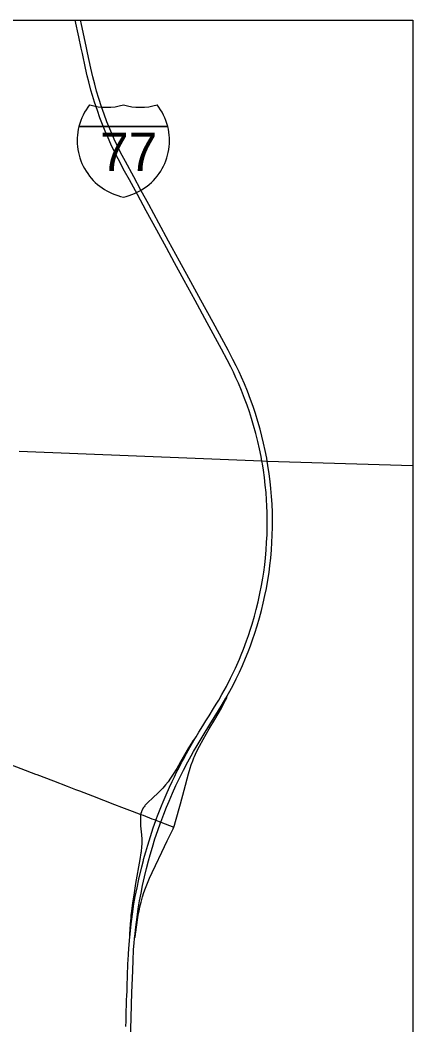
# Model space of a CAD drawing. Extents: x -12.1 to 34, y 0 to 22.
# Drawn here: x -5.572 to -4.438, y 17.405 to 20.306 of the extents above; entities that cross this region are included whole.
import ezdxf

# ---------------------------------------------------------------- set-up
doc = ezdxf.new("R2010")
doc.units = 0
for name, color, linetype in [('GM_X_Interchange_Ramps', 7, 'Continuous'), ('GM_X_Interstate_Route', 7, 'Continuous'), ('GM_X_Interstate_Shield', 7, 'Continuous'), ('GM_X_State_Route', 7, 'Continuous'), ('GM_X_Township', 7, 'Continuous'), ('SH_Text', 7, 'Continuous')]:
    doc.layers.add(name, color=color, linetype=linetype)

msp = doc.modelspace()

# ---------------------------------------------------------------- linework, layer by layer
at = {"layer": 'GM_X_Interchange_Ramps'}
for points in [[(-5.0661, 18.2332), (-5.0672, 18.2323), (-5.0686, 18.231), (-5.07, 18.2296), (-5.0728, 18.2264), (-5.0745, 18.2241), (-5.0777, 18.2186), (-5.0861, 18.2047), (-5.0973, 18.1849), (-5.109, 18.1641), (-5.1199, 18.1455), (-5.1304, 18.1287), (-5.1381, 18.117), (-5.1451, 18.107), (-5.1522, 18.0978), (-5.1603, 18.0886), (-5.1705, 18.0782), (-5.192, 18.0577), (-5.2, 18.05), (-5.2053, 18.0447), (-5.2106, 18.0392), (-5.2125, 18.0371), (-5.2143, 18.0347), (-5.2166, 18.0314), (-5.2172, 18.0304), (-5.2177, 18.0295), (-5.2181, 18.0288), (-5.2186, 18.0278), (-5.2207, 18.023), (-5.2214, 18.021), (-5.222, 18.0193), (-5.2225, 18.0179), (-5.2232, 18.015), (-5.2237, 18.0125)], [(-5.2237, 18.0125), (-5.2239, 18.0113), (-5.2241, 18.0103), (-5.2242, 18.0087), (-5.2248, 17.9955), (-5.2248, 17.9868), (-5.2245, 17.9792), (-5.2237, 17.9705), (-5.2217, 17.9532), (-5.2206, 17.941), (-5.2205, 17.9293), (-5.2212, 17.9173), (-5.2215, 17.9152), (-5.2222, 17.9097), (-5.2228, 17.9048), (-5.2233, 17.9016), (-5.2266, 17.882), (-5.2387, 17.8126), (-5.2442, 17.7793), (-5.2476, 17.7569), (-5.2507, 17.7332), (-5.252, 17.721), (-5.2528, 17.7128), (-5.2532, 17.7064), (-5.254, 17.6961), (-5.2551, 17.6807), (-5.2563, 17.6665), (-5.2566, 17.6633), (-5.2565, 17.6614), (-5.2564, 17.6594), (-5.2561, 17.6583), (-5.2557, 17.6571)], [(-5.2414, 17.656), (-5.2408, 17.657), (-5.2403, 17.6579), (-5.2399, 17.6591), (-5.2396, 17.6604), (-5.2391, 17.6636), (-5.2386, 17.6673), (-5.2379, 17.6727), (-5.233, 17.7084), (-5.2309, 17.7216), (-5.2288, 17.7331), (-5.2261, 17.7456), (-5.2228, 17.7592), (-5.2185, 17.7743), (-5.2147, 17.7866), (-5.2101, 17.7998), (-5.2048, 17.814), (-5.1986, 17.8285), (-5.1913, 17.8444), (-5.1815, 17.8649), (-5.1629, 17.9031), (-5.1471, 17.9362), (-5.138, 17.9551), (-5.1306, 17.9707), (-5.1282, 17.9761)]]:
    msp.add_lwpolyline(points, dxfattribs=at)
at = {"layer": 'GM_X_Interstate_Route'}
for points in [[(-5.0661, 18.2332), (-5.064, 18.2366), (-5.0562, 18.2496), (-5.0494, 18.2604), (-5.0415, 18.2734), (-5.0357, 18.2828), (-5.0268, 18.2972), (-5.0136, 18.3184), (-5.0061, 18.3309), (-4.9989, 18.3429), (-4.9896, 18.3591), (-4.9767, 18.3819), (-4.9644, 18.4058), (-4.9588, 18.4173), (-4.9504, 18.4352), (-4.9391, 18.4608), (-4.934, 18.4732), (-4.9275, 18.4894), (-4.9182, 18.514), (-4.9126, 18.5293), (-4.9068, 18.547), (-4.9022, 18.5615), (-4.8954, 18.585), (-4.8904, 18.6042), (-4.885, 18.6263), (-4.8798, 18.6502), (-4.8752, 18.6731), (-4.8715, 18.6943), (-4.8687, 18.7122), (-4.8661, 18.733), (-4.8639, 18.7533), (-4.8619, 18.776), (-4.8604, 18.7986), (-4.8593, 18.8202), (-4.8587, 18.8418), (-4.8586, 18.8616), (-4.8589, 18.8831), (-4.8596, 18.9035), (-4.8606, 18.921), (-4.8622, 18.9425), (-4.8643, 18.9634), (-4.8669, 18.9854), (-4.8699, 19.0067), (-4.8728, 19.0245), (-4.8743, 19.0329), (-4.8767, 19.0457), (-4.8814, 19.0686), (-4.8861, 19.0896), (-4.8919, 19.1128), (-4.898, 19.1353), (-4.9039, 19.1554), (-4.9103, 19.1754), (-4.9167, 19.1942), (-4.924, 19.2138), (-4.9331, 19.2366), (-4.9418, 19.2575), (-4.9489, 19.2735), (-4.9562, 19.2894), (-4.9637, 19.3046), (-4.9744, 19.3253), (-4.9909, 19.356), (-5.0323, 19.4323), (-5.067, 19.4963), (-5.0988, 19.5546), (-5.1263, 19.6052), (-5.1499, 19.6488), (-5.1776, 19.6994), (-5.2081, 19.7557), (-5.2335, 19.8023), (-5.2567, 19.8447), (-5.2705, 19.8703), (-5.2892, 19.9058), (-5.3002, 19.9276), (-5.3098, 19.9476), (-5.3182, 19.9661), (-5.3267, 19.9859), (-5.3343, 20.0048), (-5.3417, 20.0244), (-5.3491, 20.0452), (-5.3572, 20.0695), (-5.3632, 20.0889), (-5.3676, 20.104), (-5.3739, 20.1276), (-5.3783, 20.1457), (-5.3834, 20.1678), (-5.3923, 20.2094), (-5.3958, 20.2255), (-5.4027, 20.2578), (-5.4131, 20.3063)], [(-4.9741, 18.3554), (-4.9668, 18.3682), (-4.9575, 18.3857), (-4.9481, 18.4044), (-4.9391, 18.4233), (-4.9303, 18.443), (-4.9216, 18.4633), (-4.9139, 18.4822), (-4.9072, 18.4996), (-4.9012, 18.5166), (-4.8947, 18.5359), (-4.8878, 18.5575), (-4.8811, 18.5804), (-4.8754, 18.6012), (-4.8703, 18.6221), (-4.8653, 18.6442), (-4.8611, 18.6653), (-4.8569, 18.6894), (-4.8536, 18.7107), (-4.851, 18.7309), (-4.8486, 18.7529), (-4.8465, 18.7767), (-4.8451, 18.7976), (-4.8442, 18.8185), (-4.8436, 18.8418), (-4.8435, 18.8627), (-4.8439, 18.8848), (-4.8447, 18.9081), (-4.8461, 18.9307), (-4.848, 18.9539), (-4.8501, 18.9742), (-4.853, 18.9961), (-4.8567, 19.0203), (-4.8588, 19.0325), (-4.8603, 19.0415), (-4.8645, 19.0632), (-4.8691, 19.0842), (-4.8741, 19.1051), (-4.8794, 19.1254), (-4.8855, 19.1467), (-4.8929, 19.1706), (-4.8995, 19.1904), (-4.9068, 19.2107), (-4.916, 19.2346), (-4.9246, 19.2556), (-4.9329, 19.2748), (-4.9401, 19.2907), (-4.9482, 19.3075), (-4.9577, 19.3261), (-4.9718, 19.3529), (-5.015, 19.4328), (-5.0506, 19.4976), (-5.0847, 19.5606), (-5.1117, 19.6103), (-5.1433, 19.668), (-5.1715, 19.7196), (-5.2005, 19.7735), (-5.2234, 19.8154), (-5.244, 19.8533), (-5.2683, 19.8984), (-5.2818, 19.9242), (-5.2913, 19.9429), (-5.2973, 19.9555), (-5.3057, 19.9741), (-5.3132, 19.9918), (-5.3214, 20.0124), (-5.3296, 20.0342), (-5.3371, 20.0557), (-5.3449, 20.0801), (-5.3512, 20.1013), (-5.3566, 20.121), (-5.362, 20.1425), (-5.3678, 20.1675), (-5.3772, 20.2119), (-5.3803, 20.2258), (-5.3961, 20.2983), (-5.3978, 20.3063)], [(-5.0243, 18.2717), (-5.0115, 18.2925), (-4.9918, 18.3249), (-4.978, 18.3485), (-4.9741, 18.3554)], [(-5.1668, 17.9882), (-5.1665, 17.9891), (-5.1661, 17.9901), (-5.1572, 18.0136), (-5.1493, 18.0338), (-5.1422, 18.0509), (-5.1324, 18.0734), (-5.1223, 18.0957), (-5.1114, 18.1187), (-5.1005, 18.1401), (-5.0881, 18.1639), (-5.0784, 18.1819), (-5.0715, 18.194), (-5.0612, 18.2116), (-5.0436, 18.2405), (-5.0243, 18.2717)], [(-5.2163, 17.8792), (-5.2156, 17.882), (-5.2095, 17.9044), (-5.2038, 17.924), (-5.1961, 17.9484), (-5.1877, 17.9738), (-5.1804, 17.9947), (-5.1801, 17.9956), (-5.1735, 18.0132), (-5.1641, 18.0371), (-5.1592, 18.0489), (-5.1505, 18.0692), (-5.1405, 18.0915), (-5.1329, 18.1079), (-5.1262, 18.1215), (-5.1192, 18.1362), (-5.1142, 18.146), (-5.1058, 18.1627), (-5.1005, 18.1724), (-5.0921, 18.1883), (-5.0872, 18.197), (-5.0786, 18.2121), (-5.0707, 18.2257), (-5.0661, 18.2332)], [(-5.2434, 17.6339), (-5.243, 17.6389), (-5.2414, 17.656), (-5.241, 17.6604), (-5.2381, 17.687), (-5.2344, 17.7157), (-5.2309, 17.7395), (-5.227, 17.7629), (-5.2229, 17.7849), (-5.2185, 17.8069), (-5.2128, 17.8326), (-5.2072, 17.8564), (-5.2014, 17.8782), (-5.1966, 17.8961), (-5.19, 17.9178), (-5.1829, 17.9418), (-5.1745, 17.9661), (-5.1668, 17.9882)], [(-5.2577, 17.6339), (-5.2563, 17.6507), (-5.2557, 17.6571), (-5.2537, 17.6767), (-5.2513, 17.6969), (-5.2505, 17.7033), (-5.2467, 17.7316), (-5.2433, 17.754), (-5.2395, 17.7758), (-5.2346, 17.8004), (-5.2292, 17.8254), (-5.2208, 17.8611), (-5.2163, 17.8792)], [(-5.2667, 17.4), (-5.2662, 17.4157), (-5.2658, 17.4291), (-5.2655, 17.4454), (-5.2648, 17.4605), (-5.2645, 17.4757), (-5.2638, 17.4896), (-5.2634, 17.5024), (-5.2629, 17.5164), (-5.2619, 17.5478), (-5.2608, 17.5798), (-5.2596, 17.6066), (-5.2583, 17.6275), (-5.2577, 17.6339)], [(-5.2531, 17.3601), (-5.251, 17.4259), (-5.2491, 17.4981), (-5.2471, 17.5609), (-5.2458, 17.593), (-5.2444, 17.6191), (-5.2434, 17.6339)]]:
    msp.add_lwpolyline(points, dxfattribs=at)
at = {"layer": 'GM_X_Interstate_Shield'}
for p, q in [((-5.4021, 19.9993), (-5.1459, 19.9993)), ((-5.1459, 19.9993), (-5.4021, 19.9993)), ((-5.1459, 19.9993), (-5.4021, 19.9993))]:
    msp.add_line(p, q, dxfattribs=at)
for centre, start, end in [((-5.2407, 19.9585), 141.669, 165.8066), ((-5.3226, 20.2209), 253.0091, 286.9909), ((-5.2253, 20.2209), 253.0091, 286.9909), ((-5.3073, 19.9585), 14.1934, 38.331), ((-5.2407, 19.9585), 165.8066, 258.463), ((-5.3073, 19.9585), 281.537, 14.1934)]:
    msp.add_arc(centre, 0.1665, start, end, dxfattribs=at)
at = {"layer": 'GM_X_State_Route'}
for points in [[(-5.0706, 18.1755), (-5.0689, 18.18), (-5.0626, 18.1937), (-5.0546, 18.2093), (-5.0436, 18.2292), (-5.026, 18.2594), (-5.0099, 18.287), (-4.9911, 18.3196), (-4.9789, 18.3421), (-4.9775, 18.3453), (-4.9753, 18.3501), (-4.9741, 18.3537), (-4.9741, 18.3554)], [(-5.8303, 18.2899), (-5.8288, 18.2888), (-5.8021, 18.2701), (-5.785, 18.258), (-5.7649, 18.244), (-5.7438, 18.2295), (-5.724, 18.2163), (-5.7103, 18.2075), (-5.6958, 18.1988), (-5.6842, 18.1923), (-5.6759, 18.188), (-5.6649, 18.1828), (-5.6537, 18.178), (-5.6288, 18.1682), (-5.6027, 18.1581), (-5.5696, 18.1452), (-5.5277, 18.1292)], [(-5.1282, 17.9761), (-5.1265, 17.981), (-5.1235, 17.9919), (-5.1095, 18.0429), (-5.0987, 18.0822), (-5.0859, 18.1299), (-5.0811, 18.1461), (-5.0781, 18.1555), (-5.0739, 18.1675), (-5.0706, 18.1755)], [(-5.5277, 18.1292), (-5.5233, 18.1275), (-5.4755, 18.1092), (-5.4358, 18.0938), (-5.4119, 18.0846), (-5.4005, 18.0802), (-5.388, 18.0754), (-5.3635, 18.0661), (-5.2995, 18.0415), (-5.2789, 18.0335), (-5.249, 18.0222), (-5.2237, 18.0125), (-5.217, 18.0099), (-5.1919, 18.0002)], [(-5.1919, 18.0002), (-5.185, 17.9975), (-5.1801, 17.9956), (-5.1661, 17.9901), (-5.153, 17.985), (-5.1282, 17.9761)]]:
    msp.add_lwpolyline(points, dxfattribs=at)
at = {"layer": 'GM_X_Township'}
msp.add_lwpolyline([(-5.5749, 19.061), (-5.0665, 19.0417), (-4.8745, 19.0334), (-4.859, 19.033), (-4.4383, 19.02)], dxfattribs=at)
at = {"layer": 'SH_Text'}
msp.add_lwpolyline([(-12.1463, 20.3063), (-4.4383, 20.3063), (-4.4383, 10.9773), (-12.1463, 10.9773)], close=True, dxfattribs=at)

# ---------------------------------------------------------------- texts
at = {"layer": 'GM_X_Interstate_Shield'}
msp.add_text('77', height=0.11097, dxfattribs=at).set_placement((-5.3414, 19.8703))

doc.saveas('drawing.dxf')
